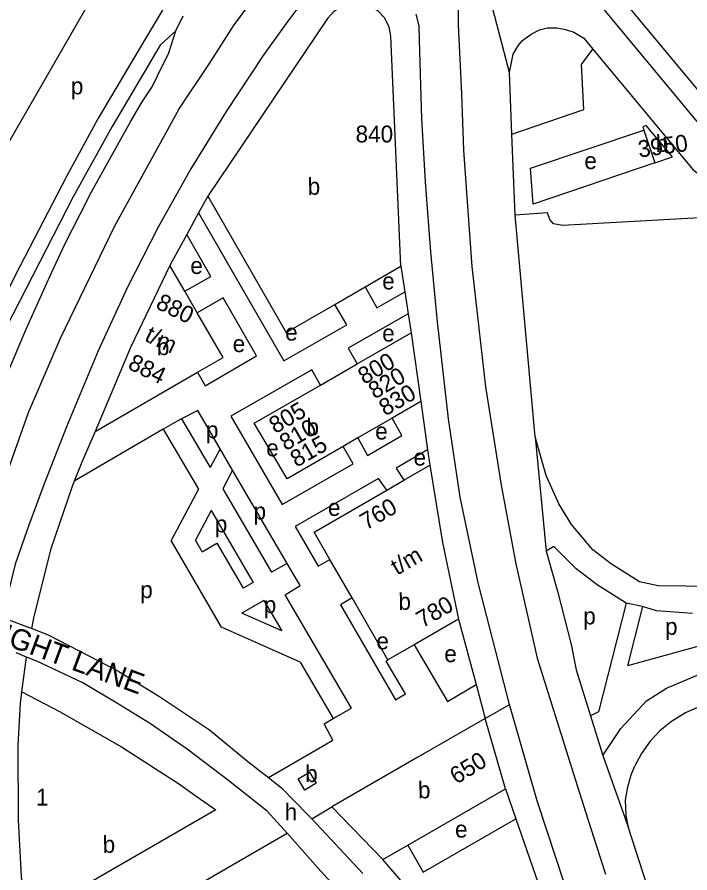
# Model space of a CAD drawing. Extents: x 154765 to 156627, y 383996 to 386132.
# Drawn here: x 155897.4 to 156057.3, y 385032.8 to 385236.2 of the extents above; entities that cross this region are included whole.
import ezdxf

# ---------------------------------------------------------------- set-up
doc = ezdxf.new("R2010")
doc.units = 0
for name, color, linetype in [('BLT_Basislijn', 7, 'Continuous'), ('BLT_Bebouwing', 7, 'Continuous'), ('BLT_Centroide', 7, 'Continuous'), ('BLT_Huisnummer', 7, 'Continuous'), ('BLT_Huisnummer_reeks', 7, 'Continuous'), ('BLT_Straatnaam', 7, 'Continuous'), ('BLT_Vlakafsluiter', 7, 'Continuous')]:
    doc.layers.add(name, color=color, linetype=linetype)

msp = doc.modelspace()

# ---------------------------------------------------------------- linework, layer by layer
at = {"layer": 'BLT_Basislijn'}
for p, q in [((155941.45, 385253.88), (155927.86, 385231.1)), ((155948.82, 385234.08), (155956.52, 385244.53)), ((156002.26, 385244.8), (156002.26, 385234.33)), ((155935.13, 385232.86), (155936.86, 385236.47)), ((155943.1, 385225.13), (155948.82, 385234.08)), ((156002.26, 385234.33), (156003.01, 385217.92)), ((155935.13, 385232.86), (155931.39, 385229.5)), ((155933.41, 385227.68), (155935.13, 385232.86)), ((155927.86, 385231.1), (155916.57, 385211.95)), ((155931.39, 385229.5), (155919.93, 385210.2)), ((156032.1, 385231.12), (156034.23, 385228.56)), ((155930.74, 385222.19), (155933.41, 385227.68)), ((155935.74, 385214.13), (155943.1, 385225.13)), ((155929.44, 385219.61), (155930.74, 385222.19)), ((156015, 385208.33), (156014.4, 385223.01)), ((155927.09, 385216), (155929.44, 385219.61)), ((156003.01, 385217.92), (156003.51, 385204.49)), ((155924.42, 385211.45), (155927.09, 385216)), ((155935.74, 385214.13), (155920.5, 385186.48)), ((155916.57, 385211.95), (155909.08, 385198.26)), ((155921.59, 385206.43), (155924.42, 385211.45)), ((155919.93, 385210.2), (155910.67, 385193.48)), ((156015.78, 385189.08), (156015, 385208.33)), ((155915.01, 385194.64), (155921.59, 385206.43)), ((156003.51, 385204.49), (156005.49, 385176.9)), ((155909.08, 385198.26), (155897.99, 385176.89)), ((155910.67, 385193.48), (155893.07, 385159.27)), ((155912.34, 385189.3), (155915.01, 385194.64)), ((155942.67, 385193.57), (155940.51, 385189.62)), ((155908.73, 385182.24), (155912.34, 385189.3)), ((155940.51, 385189.62), (155937.7, 385184.48)), ((156020.51, 385136.42), (156015.78, 385189.08)), ((155920.5, 385186.48), (155907.63, 385159.79)), ((155937.7, 385184.48), (155933.68, 385177.13)), ((155905.12, 385174.55), (155908.73, 385182.24)), ((155897.99, 385176.89), (155890.81, 385162.78)), ((155988.59, 385176.95), (155989.55, 385170.9)), ((156005.49, 385176.9), (156006.74, 385165.71)), ((155899.46, 385161.88), (155905.12, 385174.55)), ((155989.55, 385170.9), (155990.38, 385165.62)), ((155990.38, 385165.62), (155991.09, 385161.15)), ((156006.74, 385165.71), (156008.73, 385148.3)), ((155889.58, 385138.66), (155899.46, 385161.88)), ((155907.63, 385159.79), (155900.01, 385142.15)), ((156008.73, 385148.3), (156012.45, 385124.92)), ((155993.38, 385144.8), (155994.97, 385133.32)), ((155900.01, 385142.15), (155891.39, 385117.95)), ((155936.47, 385140.71), (155943.27, 385129.12)), ((155932.11, 385138.25), (155910.92, 385125.87)), ((155932.11, 385138.25), (155940.51, 385123.95)), ((155945.65, 385133.57), (155943.27, 385129.12)), ((155948.61, 385128.5), (155945.65, 385133.57)), ((155994.97, 385133.32), (155995.48, 385129.67)), ((155948.61, 385128.5), (155946.24, 385124.07)), ((155961.59, 385106.34), (155948.61, 385128.5)), ((155940.51, 385123.95), (155934.02, 385111.8)), ((155946.24, 385124.07), (155957.88, 385104.26)), ((156012.45, 385124.92), (156015.93, 385106.27)), ((155943.48, 385118.9), (155939.74, 385111.9)), ((155943.48, 385118.9), (155953.52, 385101.81)), ((155945.95, 385091.2), (155934.02, 385111.8)), ((155941.36, 385109.1), (155939.74, 385111.9)), ((156024.96, 385110.36), (156023.16, 385109.26)), ((156030.27, 385105.06), (156024.96, 385110.36)), ((156038.7, 385106.16), (156034.23, 385109.58)), ((156023.16, 385109.26), (156025.85, 385099.75)), ((155961.59, 385106.34), (155957.88, 385104.26)), ((156015.93, 385106.27), (156021.04, 385083.82)), ((156045.37, 385101.94), (156038.7, 385106.16)), ((156035.27, 385101.23), (156030.27, 385105.06)), ((155953.52, 385101.81), (155951.09, 385100.44)), ((156025.85, 385099.75), (156029.09, 385087.08)), ((156042.17, 385096.87), (156035.27, 385101.23)), ((155956.06, 385097.5), (155950.77, 385094.53)), ((155956.06, 385097.5), (155960.3, 385090.28)), ((156041.04, 385097.64), (156040.87, 385097.69)), ((156042.17, 385096.87), (156035.57, 385071.09)), ((156046.09, 385096.07), (156042.17, 385096.87)), ((156046.09, 385096.07), (156042.49, 385082)), ((156090.94, 385095.33), (156042.49, 385082)), ((156049.41, 385095.04), (156046.09, 385096.07)), ((155898.37, 385091.75), (155893.77, 385093.52)), ((155960.3, 385090.28), (155950.77, 385094.53)), ((156057.95, 385094.45), (156049.41, 385095.04)), ((155900.74, 385090.85), (155898.37, 385091.75)), ((155964.66, 385082.86), (155945.95, 385091.2)), ((156002.32, 385093.09), (156006.51, 385077.55)), ((155904.83, 385089.28), (155900.74, 385090.85)), ((155912.05, 385085.53), (155904.83, 385089.28)), ((155921.57, 385080.62), (155912.05, 385085.53)), ((156029.09, 385087.08), (156030.3, 385081.03)), ((155899.57, 385084.09), (155897.1, 385085.07)), ((155898.47, 385075.8), (155899.57, 385084.09)), ((155902.22, 385083.03), (155899.57, 385084.09)), ((155912.82, 385078.06), (155902.22, 385083.03)), ((155964.66, 385082.86), (155972.53, 385069.46)), ((155921.57, 385080.62), (155931.25, 385074.74)), ((155920.82, 385073.3), (155912.82, 385078.06)), ((156006.51, 385077.55), (156008.67, 385069.52)), ((155929.08, 385068.22), (155920.82, 385073.3)), ((155931.25, 385074.74), (155943.07, 385066.77)), ((156008.67, 385069.52), (156014.47, 385072.85)), ((156035.57, 385071.09), (156033.72, 385070.1)), ((155937.77, 385062.19), (155929.08, 385068.22)), ((155943.07, 385066.77), (155952.24, 385059.29)), ((155947.66, 385054.71), (155937.77, 385062.19)), ((155952.24, 385059.29), (155957.1, 385055.46)), ((155956.84, 385047.48), (155947.66, 385054.71)), ((155957.1, 385055.46), (155960.2, 385053.02)), ((155960.2, 385053.02), (155966.58, 385046.55)), ((156013.47, 385052.77), (156015.93, 385045.61)), ((155961.53, 385042.24), (155956.84, 385047.48)), ((155967.42, 385045.65), (155966.58, 385046.55)), ((155967.42, 385045.65), (155972.2, 385048.47)), ((156032.54, 385047.32), (156037.29, 385032.48)), ((155979.56, 385032.63), (155967.42, 385045.65)), ((155931.17, 385024.69), (155961.53, 385042.24)), ((155968.89, 385034.02), (155961.53, 385042.24)), ((155981.88, 385019.64), (155968.89, 385034.02))]:
    msp.add_line(p, q, dxfattribs=at)
for points in [[(155895.26, 385206.11), (155915.21, 385240.91), (155925.88, 385257.56), (155936.99, 385273.7)], [(156017.6, 385268.87), (156067.1, 385209.39), (156078.36, 385200.71), (156097.68, 385191.32), (156111.76, 385183.48), (156119.51, 385177.89), (156134.36, 385164.83), (156170.3, 385125.55)], [(155966.13, 385241.1), (155961.71, 385235.19), (155956.06, 385227.3), (155947.04, 385213.69), (155938.68, 385200.08), (155930.93, 385186.27), (155923.58, 385171.96), (155916.6, 385156.84), (155909.11, 385138.81), (155903.8, 385125.22)], [(156035.25, 385239.85), (156063.61, 385205.77), (156075.71, 385196.44), (156095.37, 385186.88), (156109.07, 385179.25), (156116.39, 385173.98), (156130.85, 385161.25), (156164.98, 385123.97)], [(156014.47, 385072.85), (156006.96, 385101.7), (156002.74, 385122.1), (155999.9, 385140.67), (155997.35, 385163.71), (155995.71, 385180.36), (155994.45, 385196.98), (155993.56, 385211.99), (155993.03, 385230.65), (155992.94, 385234.07), (155992.22, 385236.86)], [(156014.4, 385223.01), (156015.33, 385227.35), (156016.59, 385229.47), (156017.55, 385230.62), (156019.61, 385232.13), (156021.58, 385233.16), (156023.44, 385233.62), (156025.73, 385233.57), (156027.76, 385233.23), (156029.75, 385232.56), (156032.1, 385231.12)], [(156015, 385208.33), (156032.15, 385214.23), (156031.59, 385224.93), (156034.23, 385228.56)], [(156034.23, 385228.56), (156058.03, 385199.97), (156068.43, 385191.96)], [(156049.03, 385201.53), (156020.05, 385191.7), (156019.44, 385200.28), (156046.39, 385209.31)], [(155940.51, 385189.62), (155960.8, 385154.47), (155975.73, 385163), (155972.88, 385167.87)], [(156073.89, 385189.27), (156027.06, 385186.63), (156024.89, 385187.06), (156024.01, 385188.04), (156023.51, 385189.61), (156015.78, 385189.08)], [(155937.21, 385171.02), (155943.45, 385174.51), (155937.7, 385184.48)], [(155980.13, 385172.06), (155982.89, 385167.1), (155989.55, 385170.9)], [(155940.27, 385151.76), (155942.08, 385148.51), (155954.31, 385155.7), (155946.37, 385169.45), (155940.17, 385165.88)], [(155990.38, 385165.62), (155976.1, 385157.46), (155978.22, 385153.74)], [(155969.5, 385148.72), (155967.44, 385152.31), (155948.17, 385141.3), (155960.41, 385120.34), (155977.25, 385130.03), (155974.91, 385134.14)], [(155945.65, 385133.57), (155940.32, 385142.66), (155936.47, 385140.71)], [(155936.47, 385140.71), (155935.39, 385140.16), (155932.11, 385138.25)], [(155978.39, 385136.14), (155980.69, 385131.98), (155988.86, 385136.74), (155986.55, 385140.86)], [(155915.93, 385137.7), (155912.74, 385130.37), (155910.92, 385125.87)], [(156034.23, 385109.58), (156029.21, 385115.59), (156026.16, 385120.47), (156023.12, 385127.25), (156020.51, 385136.42)], [(155994.97, 385133.32), (155987.46, 385128.96), (155989.3, 385126.1)], [(155910.92, 385125.87), (155910.5, 385124.84), (155905.36, 385109.81), (155901.32, 385093.75), (155900.74, 385090.85)], [(155985.27, 385123.77), (155983.31, 385126.54), (155963.5, 385115.11), (155968.92, 385105.67), (155971.74, 385107.3)], [(155903.8, 385125.22), (155900.13, 385115.42), (155896.89, 385106.17), (155893.77, 385093.52)], [(155941.36, 385109.1), (155944.88, 385111.14), (155951.09, 385100.44)], [(155961.07, 385098.84), (155964.68, 385101.07), (155961.59, 385106.34)], [(156069.44, 385100.74), (156049.82, 385101.02), (156045.37, 385101.94)], [(155972.53, 385069.46), (155976.87, 385071.96), (155961.07, 385098.84)], [(155977.04, 385098.14), (155974.24, 385096.53), (155987.33, 385073.94), (155989.68, 385075.32), (155985.1, 385083.14), (155985.54, 385083.4)], [(155991.8, 385087.02), (155999.69, 385073.49), (156006.51, 385077.55)], [(156021.04, 385083.82), (156029.66, 385056.32), (156032.54, 385047.32)], [(156030.3, 385081.03), (156033.72, 385070.1)], [(156046.99, 385073.68), (156051.75, 385076.72), (156059.43, 385079.93)], [(156036.66, 385060.73), (156040.9, 385067.07), (156046.99, 385073.68)], [(156062.38, 385073.27), (156059.26, 385072.15), (156056.28, 385070.81), (156052.97, 385068.76), (156050.21, 385066.58), (156047.87, 385064.06), (156045.83, 385061.19), (156044.27, 385058.22)], [(156061.74, 384943.77), (156054.93, 384958.46), (156049.32, 384971.64), (156039.1, 384997.76), (156029.81, 385023.21), (156021.05, 385049.93), (156014.47, 385072.85)], [(155957.1, 385055.46), (155972.4, 385064.33), (155970.4, 385068.22), (155972.53, 385069.46)], [(156033.72, 385070.1), (156036.66, 385060.73)], [(156042.75, 385043.48), (156042.17, 385046.51), (156042.03, 385050.09), (156042.59, 385053.25), (156043.4, 385056.08), (156044.27, 385058.22)], [(156015.93, 385045.61), (156033.06, 384996.37), (156029.14, 384994.1), (156025.03, 384992.84), (156021.02, 384990.55), (156015.24, 385000), (155984.29, 385035.94)], [(155990.25, 385039.37), (155993.89, 385032.97), (156015.93, 385045.61)], [(156136, 384858.96), (156115.57, 384891.11), (156096.29, 384922.61), (156080.28, 384952.51), (156069.18, 384974.46), (156063, 384988.46), (156057.67, 385001.26), (156052.62, 385013.66), (156046.98, 385030.26), (156042.75, 385043.48)]]:
    msp.add_lwpolyline(points, dxfattribs=at)
at = {"layer": 'BLT_Bebouwing'}
for p, q in [((155971.18, 385235.84), (155942.67, 385193.57)), ((155988.59, 385176.95), (155986.21, 385231.6)), ((156046.39, 385209.31), (156049.03, 385201.53)), ((155942.67, 385193.57), (155961.35, 385161.21)), ((155933.68, 385177.13), (155924.28, 385157.65)), ((155937.21, 385171.02), (155933.68, 385177.13)), ((155980.13, 385172.06), (155988.59, 385176.95)), ((155940.17, 385165.88), (155937.21, 385171.02)), ((155972.88, 385167.87), (155980.13, 385172.06)), ((155961.35, 385161.21), (155972.88, 385167.87)), ((155946.32, 385155.25), (155940.17, 385165.88)), ((155978.22, 385153.74), (155991.09, 385161.15)), ((155991.09, 385161.15), (155993.38, 385144.8)), ((155924.28, 385157.65), (155915.93, 385137.7)), ((155940.27, 385151.76), (155946.32, 385155.25)), ((155969.5, 385148.72), (155978.22, 385153.74)), ((155915.93, 385137.7), (155940.27, 385151.76)), ((155993.38, 385144.8), (155986.55, 385140.86)), ((155986.55, 385140.86), (155978.39, 385136.14)), ((155978.39, 385136.14), (155974.91, 385134.14)), ((155989.3, 385126.1), (155995.48, 385129.67)), ((155985.27, 385123.77), (155989.3, 385126.1)), ((155977.04, 385098.14), (155971.74, 385107.3)), ((155985.54, 385083.4), (155977.04, 385098.14)), ((156002.32, 385093.09), (155991.8, 385087.02)), ((155991.8, 385087.02), (155985.54, 385083.4)), ((156013.47, 385052.77), (156008.67, 385069.52)), ((155990.25, 385039.37), (156013.47, 385052.77)), ((155972.2, 385048.47), (155984.29, 385035.94)), ((155984.29, 385035.94), (155990.25, 385039.37))]:
    msp.add_line(p, q, dxfattribs=at)
for points in [[(155986.21, 385231.6), (155985.81, 385233.78), (155984.79, 385235.87), (155983.2, 385237.6), (155981.25, 385238.79), (155979.16, 385239.38), (155976.88, 385239.39), (155974.62, 385238.74), (155972.65, 385237.49), (155971.18, 385235.84)], [(156049.03, 385201.53), (156053.19, 385202.94), (156046.97, 385210.41), (156046.12, 385210.12), (156046.39, 385209.31)], [(155974.91, 385134.14), (155961.55, 385126.42), (155953.76, 385139.65), (155969.5, 385148.72)], [(155995.48, 385129.67), (155998.47, 385111.3), (156002.32, 385093.09)], [(155971.74, 385107.3), (155967.99, 385113.8), (155985.27, 385123.77)], [(155899.6, 385021.83), (155898.36, 385031.96), (155897.72, 385045.37), (155897.61, 385063.18), (155898.17, 385073.01), (155898.47, 385075.8)], [(155898.47, 385075.8), (155907.47, 385071.11), (155922.15, 385062.79), (155935.76, 385054.02), (155940.18, 385050.9), (155944.6, 385047.79), (155899.6, 385021.83)], [(156008.67, 385069.52), (155992.63, 385060.26)], [(155992.63, 385060.26), (155972.2, 385048.47)]]:
    msp.add_lwpolyline(points, dxfattribs=at)
msp.add_lwpolyline([(155965.79, 385052.49), (155964.22, 385055.18), (155966.91, 385056.74), (155968.47, 385054.08)], close=True, dxfattribs=at)
at = {"layer": 'BLT_Vlakafsluiter'}
for p, q in [((156014.4, 385223.01), (156010.53, 385237.8)), ((156020.51, 385136.42), (156023.16, 385109.26)), ((156036.66, 385060.73), (156042.75, 385043.48))]:
    msp.add_line(p, q, dxfattribs=at)

# ---------------------------------------------------------------- texts
at = {"layer": 'BLT_Centroide'}
for s, p in [('p', (155910.13, 385217.8)), ('e', (156032.23, 385200.04)), ('e', (155938.55, 385175.12)), ('e', (155984.17, 385171.45)), ('e', (155961.1, 385159.28)), ('e', (155984.17, 385159.07)), ('e', (155948.62, 385156.55)), ('p', (155942.26, 385136.06)), ('e', (155982.5, 385135.78)), ('e', (155956.59, 385131.79)), ('e', (155991.62, 385129.59)), ('p', (155953.58, 385116.76)), ('e', (155971.27, 385117.63)), ('p', (155944.36, 385113.72)), ('p', (155926.63, 385098.09)), ('p', (155956, 385094.52)), ('p', (156031.98, 385091.84)), ('p', (156051.43, 385089.35)), ('e', (155982.79, 385085.92)), ('e', (155998.94, 385082.88)), ('h', (155960.97, 385045.28)), ('e', (156001.49, 385041.19))]:
    msp.add_text(s, height=4, dxfattribs=at).set_placement(p)
for p in [(156049.26, 385204.12), (155966.48, 385193.91), (155930.62, 385155.8), (155966.2, 385136.75), (155988.06, 385095.28), (155965.89, 385054.36), (155992.71, 385050.49), (155917.73, 385037.55)]:
    msp.add_text('b', height=4, rotation=1, dxfattribs=at).set_placement(p)
at = {"layer": 'BLT_Huisnummer'}
for s, p in [('840', (155977.84, 385206.38)), ('1', (155901.86, 385048.81))]:
    msp.add_text(s, height=4, dxfattribs=at).set_placement(p)
for s, rotation, p in [('3950', 7.7425, (156045.26, 385202.77)), ('650', 31.6697, (156001.82, 385053.74))]:
    msp.add_text(s, height=4, rotation=rotation, dxfattribs=at).set_placement(p)
at = {"layer": 'BLT_Huisnummer_reeks'}
for s, rotation, p in [('880', 333.9169, (155930.07, 385167.09)), ('t/m', 333.9169, (155927.43, 385159.38)), ('800', 30.0007, (155979.88, 385148.74)), ('884', 333.9169, (155923.44, 385152.72)), ('820', 30.0007, (155982.37, 385145.27)), ('830', 30.0007, (155984.87, 385141.24)), ('805', 30.0007, (155958.73, 385137.04)), ('810', 30.0007, (155961.23, 385132.99)), ('815', 30.0007, (155963.79, 385129.05)), ('760', 30.0013, (155980.36, 385114.16)), ('t/m', 30.0013, (155987.7, 385103.43)), ('780', 30.0013, (155993.74, 385090.91))]:
    msp.add_text(s, height=4, rotation=rotation, dxfattribs=at).set_placement(p)
at = {"layer": 'BLT_Straatnaam'}
msp.add_text('FLIGHT LANE', height=5, rotation=339.6933, dxfattribs=at).set_placement((155885.96, 385090.09))

doc.saveas('drawing.dxf')
